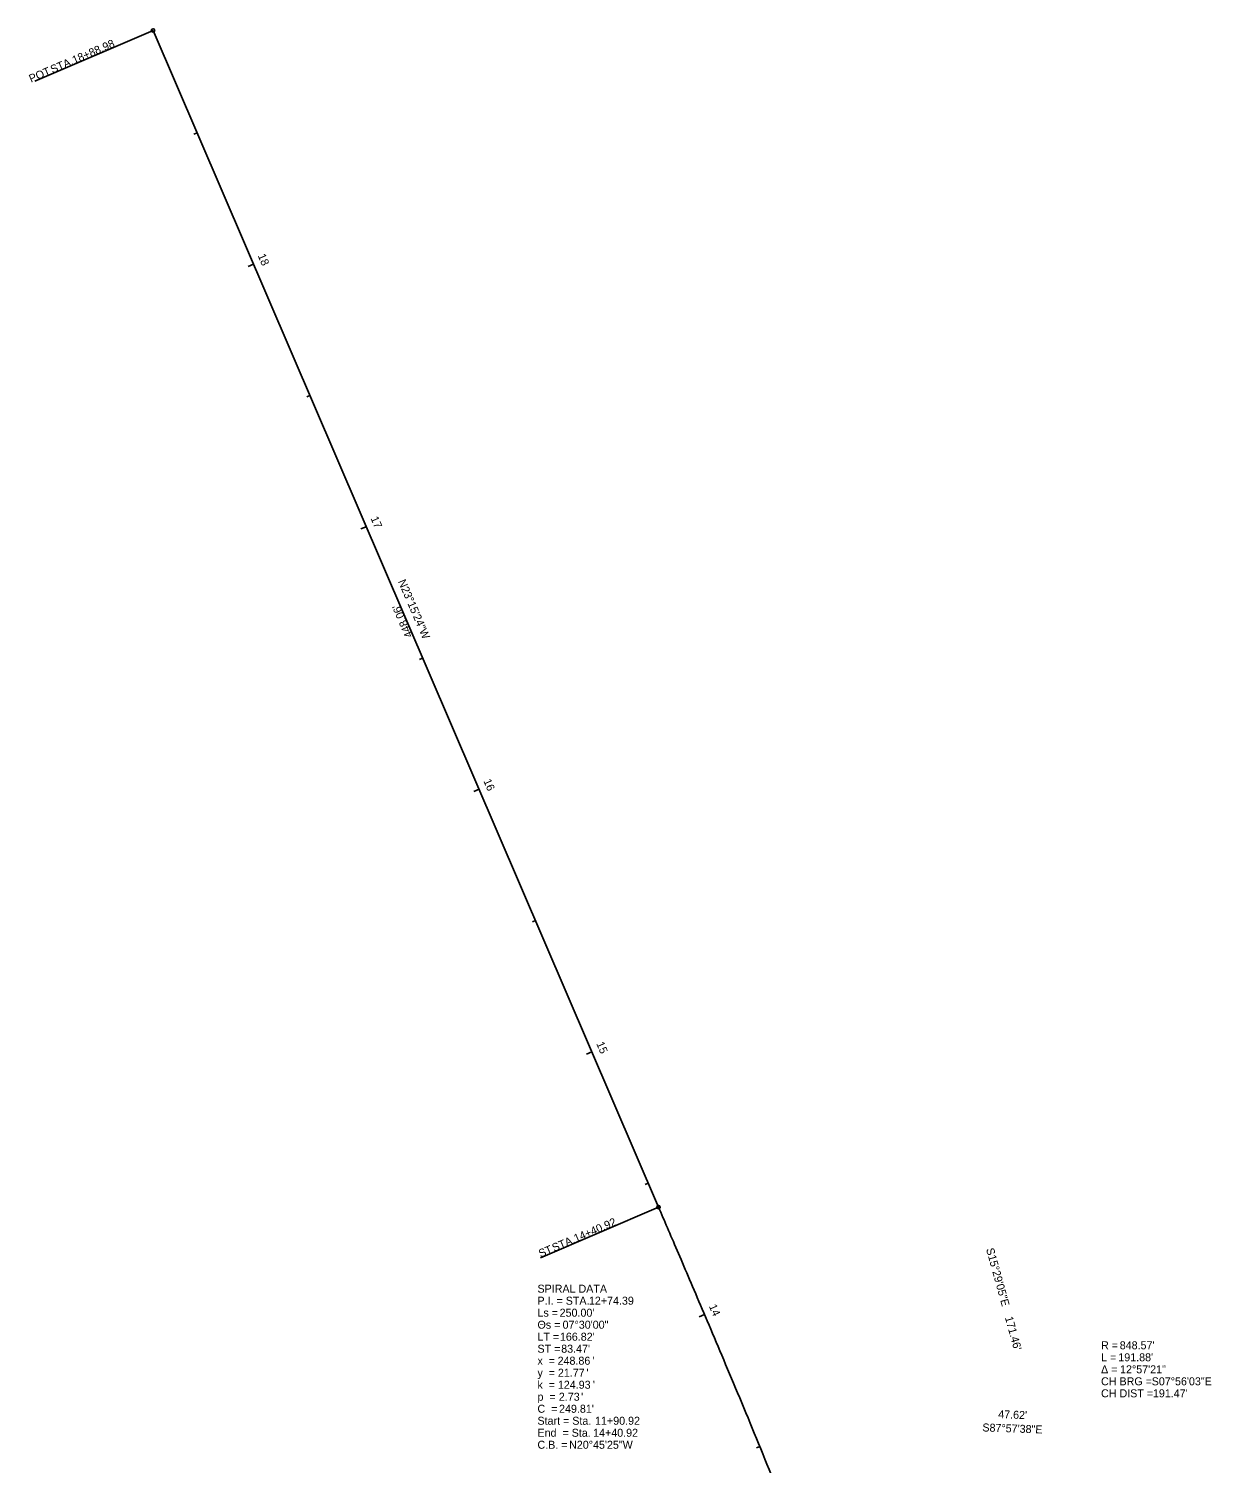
# Model space of a CAD drawing. Extents: x 1609531 to 1610891, y 471231 to 473177.
# Drawn here: x 1609772 to 1610186, y 472675 to 473177 of the extents above; entities that cross this region are included whole.
import ezdxf

# ---------------------------------------------------------------- set-up
doc = ezdxf.new("R2010")
doc.units = 0
for name, color, linetype in [('BR_X_SV_Shot_Marker', 7, 'Continuous'), ('Default', 7, 'Continuous'), ('PV_X_Driveway', 7, 'Continuous'), ('PV_X_EOP', 7, 'Continuous'), ('PV_X_Shoulder_Aggregate', 7, 'Continuous'), ('RD_X_GR_Lt', 7, 'Continuous'), ('SV_X_Control_Cells_Found', 7, 'Continuous'), ('UT_X_Misc_Cells', 7, 'Continuous'), ('UT_X_Telecom_Cells', 7, 'Continuous'), ('UT_X_Water', 7, 'Continuous')]:
    doc.layers.add(name, color=color, linetype=linetype)

msp = doc.modelspace()

# ---------------------------------------------------------------- linework, layer by layer
at = {"layer": 'Default'}
msp.add_line((1609992.82, 472764.38), (1609815.9, 473176.03), dxfattribs=at)
msp.add_open_spline([(1610081.35, 472530.78), (1610079.94, 472535.8), (1610077.03, 472545.8), (1610070.9, 472565.71), (1610062.71, 472590.43), (1610052.15, 472619.85), (1610041, 472649.04), (1610029.36, 472678.05), (1610017.38, 472706.91), (1610007.19, 472730.87), (1609998.99, 472750.02), (1609994.87, 472759.59), (1609992.82, 472764.38)], degree=3, dxfattribs=at)
at = {"layer": 'PV_X_Shoulder_Aggregate'}
for p, q in [((1609831.29, 473140.22), (1609830.19, 473139.74)), ((1609851.04, 473094.28), (1609849.2, 473093.49)), ((1609870.78, 473048.34), (1609869.68, 473047.87)), ((1609890.52, 473002.41), (1609888.68, 473001.62)), ((1609910.26, 472956.47), (1609909.16, 472955.99)), ((1609930.01, 472910.53), (1609928.17, 472909.74)), ((1609949.75, 472864.59), (1609948.65, 472864.12)), ((1609969.49, 472818.66), (1609967.65, 472817.87)), ((1609989.23, 472772.72), (1609988.13, 472772.25)), ((1610008.93, 472726.76), (1610007.09, 472725.98)), ((1610028.24, 472680.64), (1610027.12, 472680.19))]:
    msp.add_line(p, q, dxfattribs=at)
at = {"layer": 'SV_X_Control_Cells_Found'}
for p, q in [((1609815.9, 473176.03), (1609774.56, 473158.26)), ((1609992.82, 472764.38), (1609951.47, 472746.61))]:
    msp.add_line(p, q, dxfattribs=at)
for centre in [(1609815.9, 473176.03), (1609992.82, 472764.38)]:
    msp.add_circle(centre, 0.6, dxfattribs=at)
at = {"layer": 'UT_X_Misc_Cells'}
msp.add_line((1609992.82, 472764.38), (1609815.9, 473176.03), dxfattribs=at)
msp.add_open_spline([(1610081.35, 472530.78), (1610079.94, 472535.8), (1610077.03, 472545.8), (1610070.9, 472565.71), (1610062.71, 472590.43), (1610052.15, 472619.85), (1610041, 472649.04), (1610029.36, 472678.05), (1610017.38, 472706.91), (1610007.19, 472730.87), (1609998.99, 472750.02), (1609994.87, 472759.59), (1609992.82, 472764.38)], degree=3, dxfattribs=at)

# ---------------------------------------------------------------- texts
at = {"layer": 'BR_X_SV_Shot_Marker'}
for s, p in [('SPIRAL DATA', (1609950.45, 472734.43)), ('P.I. = STA. ', (1609950.45, 472730.23)), ('12+74.39', (1609968.45, 472730.23)), ('Θs = ', (1609950.45, 472721.83)), ('Ls = ', (1609950.45, 472726.03)), ("250.00'", (1609958.2, 472726.03)), ('07°30\'00"', (1609959.24, 472721.83)), ('LT = ', (1609950.45, 472717.63)), ("166.82'", (1609958.3, 472717.63)), ('ST = ', (1609950.45, 472713.43)), ("83.47'", (1609958.75, 472713.43)), ('x  = ', (1609950.45, 472709.23)), ('248.86', (1609957.49, 472709.23)), ("'", (1609969.74, 472709.23)), ('y  = ', (1609950.45, 472705.03)), ('21.77', (1609957.59, 472705.03)), ("'", (1609967.6, 472705.03)), ('k  = ', (1609950.45, 472700.83)), ('124.93', (1609957.59, 472700.83)), ('2.73', (1609957.93, 472696.63)), ("'", (1609965.72, 472696.63)), ("'", (1609969.84, 472700.83)), ('C  = ', (1609950.45, 472692.43)), ('p  = ', (1609950.45, 472696.63)), ("249.81'", (1609958, 472692.43)), ('Start = Sta. ', (1609950.45, 472688.23)), ('11+90.92', (1609970.6, 472688.23)), ('End  = Sta. ', (1609950.45, 472684.03)), ('14+40.92', (1609969.92, 472684.03)), ('C.B. = ', (1609950.45, 472679.83)), ('N20°45\'25"W', (1609961.52, 472679.83))]:
    msp.add_text(s, height=2.8, dxfattribs=at).set_placement(p)
at = {"layer": 'PV_X_Driveway'}
msp.add_text("47.62'", height=2.8, rotation=357.9606, dxfattribs=at).set_placement((1610111.67, 472690.55))
at = {"layer": 'PV_X_EOP'}
msp.add_text("448.06'", height=2.8, rotation=113.2567, dxfattribs=at).set_placement((1609906.87, 472964.28))
at = {"layer": 'PV_X_Shoulder_Aggregate'}
for s, rotation, p in [('18', 293.2567, (1609852.49, 473097.23)), ('17', 293.2567, (1609891.98, 473005.35)), ('16', 293.2567, (1609931.46, 472913.48)), ('15', 293.2567, (1609970.96, 472821.56)), ('14', 293.0557, (1610010.39, 472729.73))]:
    msp.add_text(s, height=2.8, rotation=rotation, dxfattribs=at).set_placement(p)
at = {"layer": 'RD_X_GR_Lt'}
msp.add_text('S87°57\'38"E', height=2.8, rotation=357.9606, dxfattribs=at).set_placement((1610106.12, 472685.91))
at = {"layer": 'SV_X_Control_Cells_Found'}
for s, p in [('18+88.98', (1609788.31, 473164.22)), ('POT', (1609773.2, 473157.72)), (' STA. ', (1609779.75, 473160.53)), ('14+40.92', (1609963.88, 472751.98)), ('ST', (1609951.54, 472746.68)), (' STA. ', (1609955.31, 472748.3))]:
    msp.add_text(s, height=2.8, rotation=23.2567, dxfattribs=at).set_placement(p)
at = {"layer": 'UT_X_Telecom_Cells'}
msp.add_text('N23°15\'24"W', height=2.8, rotation=293.2567, dxfattribs=at).set_placement((1609901.58, 472983.25))
at = {"layer": 'UT_X_Water'}
for s, p in [('S15°29\'05"E', (1610107.43, 472749.66)), ("171.46'", (1610114.03, 472725.73))]:
    msp.add_text(s, height=2.8, rotation=285.4848, dxfattribs=at).set_placement(p)
for s, p in [('R = ', (1610147.7, 472714.63)), ("848.57'", (1610154.24, 472714.63)), ('L = ', (1610147.7, 472710.43)), ("191.88'", (1610153.74, 472710.43)), ('Δ = ', (1610147.7, 472706.23)), ('CH BRG = ', (1610147.7, 472702.03)), ('12°57\'21"', (1610154.35, 472706.23)), ('S07°56\'03"E', (1610165.42, 472702.03)), ('CH DIST = ', (1610147.7, 472697.83)), ("191.47'", (1610165.85, 472697.83))]:
    msp.add_text(s, height=2.8, dxfattribs=at).set_placement(p)

doc.saveas('drawing.dxf')
